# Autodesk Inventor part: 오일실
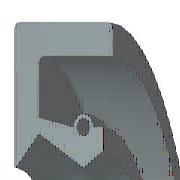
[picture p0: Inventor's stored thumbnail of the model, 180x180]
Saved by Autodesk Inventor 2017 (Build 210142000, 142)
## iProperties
Created: 2021-07
Part Number: 오일실
Material: 고무
Description: 오일-실
Document SubType Name: Modeling
Standard: KS B 2804
Designer: mdu
Standards Organization: KS
Language: ko-KR
Size Designation: D - 10 20 7
Categories: <MemberInstance><Categories><Category DisplayName="샤프트 부품" InternalName="7f7aeb1f-a693-4053-b835-cee3144e0d98" Mnemonic="SHFT"><Category DisplayName="실링" Intern
Density: 0.93 g/cm^3
Mass: 1.11329 g
Surface Area: 16.3871 cm^2
Volume: 1.19708 cm^3
Appearance: 고무 - 검은색 - 버전 1.1
IsCustomPart: 0
Author: mdu
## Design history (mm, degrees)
revolve "본체" stored, may be unused: angle "d17" = 90 deg
revolve "스프링1" stored, may be unused: angle "d18" = 90 deg
body "Solid1"
sketch "스케치1"
  geometry: L1 (0, 10)-(7, 10); L2 (7, 8.25)-(1.75, 8.25); L3 (1.75, 6.75)-(4.9, 5); L4 (4.9, 5)-(0, 5); L5 (0, 0)-(9.586, 0) reference; L6 (4.9, 5)-(6.3, 5.875); L7 (0, 18)-(0, -3) reference; L8 (-1.941, 0)-(11.507, 0) reference; L9 (4.2, 7.1)-(1.75, 7.59); L10 (1.75, 7.59)-(1.75, 8.25); L11 (0, 10)-(0, 5.088); L12 (4.9, 5)-(0, 5); L13 (1.75, 6.75)-(0.152, 5.028); L14 (7, 10)-(7, 8.25); L15 (5.6, 7.1)-(6.3, 7.1); L16 (6.3, 7.1)-(6.3, 5.875); C1 r 0.455 at (4.9, 7.1); A1 r 0.7 centre (4.9, 7.1) between (5.6, 7.1) and (4.2, 7.1); A2 r 0.088 centre (0.088, 5.088) between (0, 5.088) and (0.152, 5.028); 1 further point
  constraints: 28 end point, 5 horizontal alignment, 5 point on line, 4 point on circle, 4 vertical alignment, 3 centre point, 3 tangent, 2 collinear, 2 horizontal, 2 perpendicular, 1 coincident, 1 parallel
  dimensions: "d0" = 20 diameter of L1 L5 (= SD2); "d1" = 1.75 distance of L1.end L2.start (= SD); "d2" = 0.91 diameter of C1 (= SPDI); "d3" = 1.4 diameter of A1 (= SPDA); "d4" = 10 diameter of L3.end L5 (= NND); "d5" = 13.5 diameter of L3.start L5 (= TKDM); "d7" = 15.18 diameter of L9.end L5 (= TKDM + 0.24 x SWDT); "d8" = 1.75 distance between parallel lines of L11 L10 (= SD); "d9" = 4.9 distance from line of L11 C1.centre (= SPDST); "d10" = 14.2 diameter of C1.centre L5 (= HLDM); "d11" = 0.0875 radius of A2 (= 0.25 x LAB); "d12" = 6.3 distance between parallel lines of L11 L16 (= SDI); "d13" = 11.75 diameter of L6.end L5 (= ABDM); "d14" = 7 distance from line of L11 L1.end (= SWDT)
fillet "모깎기1" dims "d6" = 0.3 (= RR)
other parameters: "SD2" = 20 [user parameter; used in 1 equation term], "SWDT" = 7 [user parameter; used in 2 equation terms], "RR" = 0.3 [user parameter; used in 1 equation term], "SD" = 1.75 [user parameter; used in 2 equation terms], "NND" = 10 [user parameter; used in 1 equation term], "SPDA" = 1.4 [user parameter; used in 1 equation term], "SPDI" = 0.91 [user parameter; used in 1 equation term], "TKDM" = 13.5 [user parameter; used in 2 equation terms], "HLDM" = 14.2 [user parameter; used in 1 equation term], "ABDM" = 11.75 [user parameter; used in 1 equation term], "SDI" = 6.3 [user parameter; used in 1 equation term], "SPDST" = 4.9 [user parameter; used in 1 equation term], "LAB" = 0.35 [user parameter; used in 1 equation term], "d15" = 0, "d16" = 0, "d19" = 0
